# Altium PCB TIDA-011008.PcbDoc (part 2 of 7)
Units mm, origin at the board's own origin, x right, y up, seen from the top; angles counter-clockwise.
Board outline 252 x 205 mm, 4 copper layers (Top Layer, Inner Layer 1, Inner Layer 2, Bottom Layer), stack 1.926 mm thick; 517 components, 293 nets, 1426 pads, 1855 vias.
Unrouted connection lines stored in the file: 4.
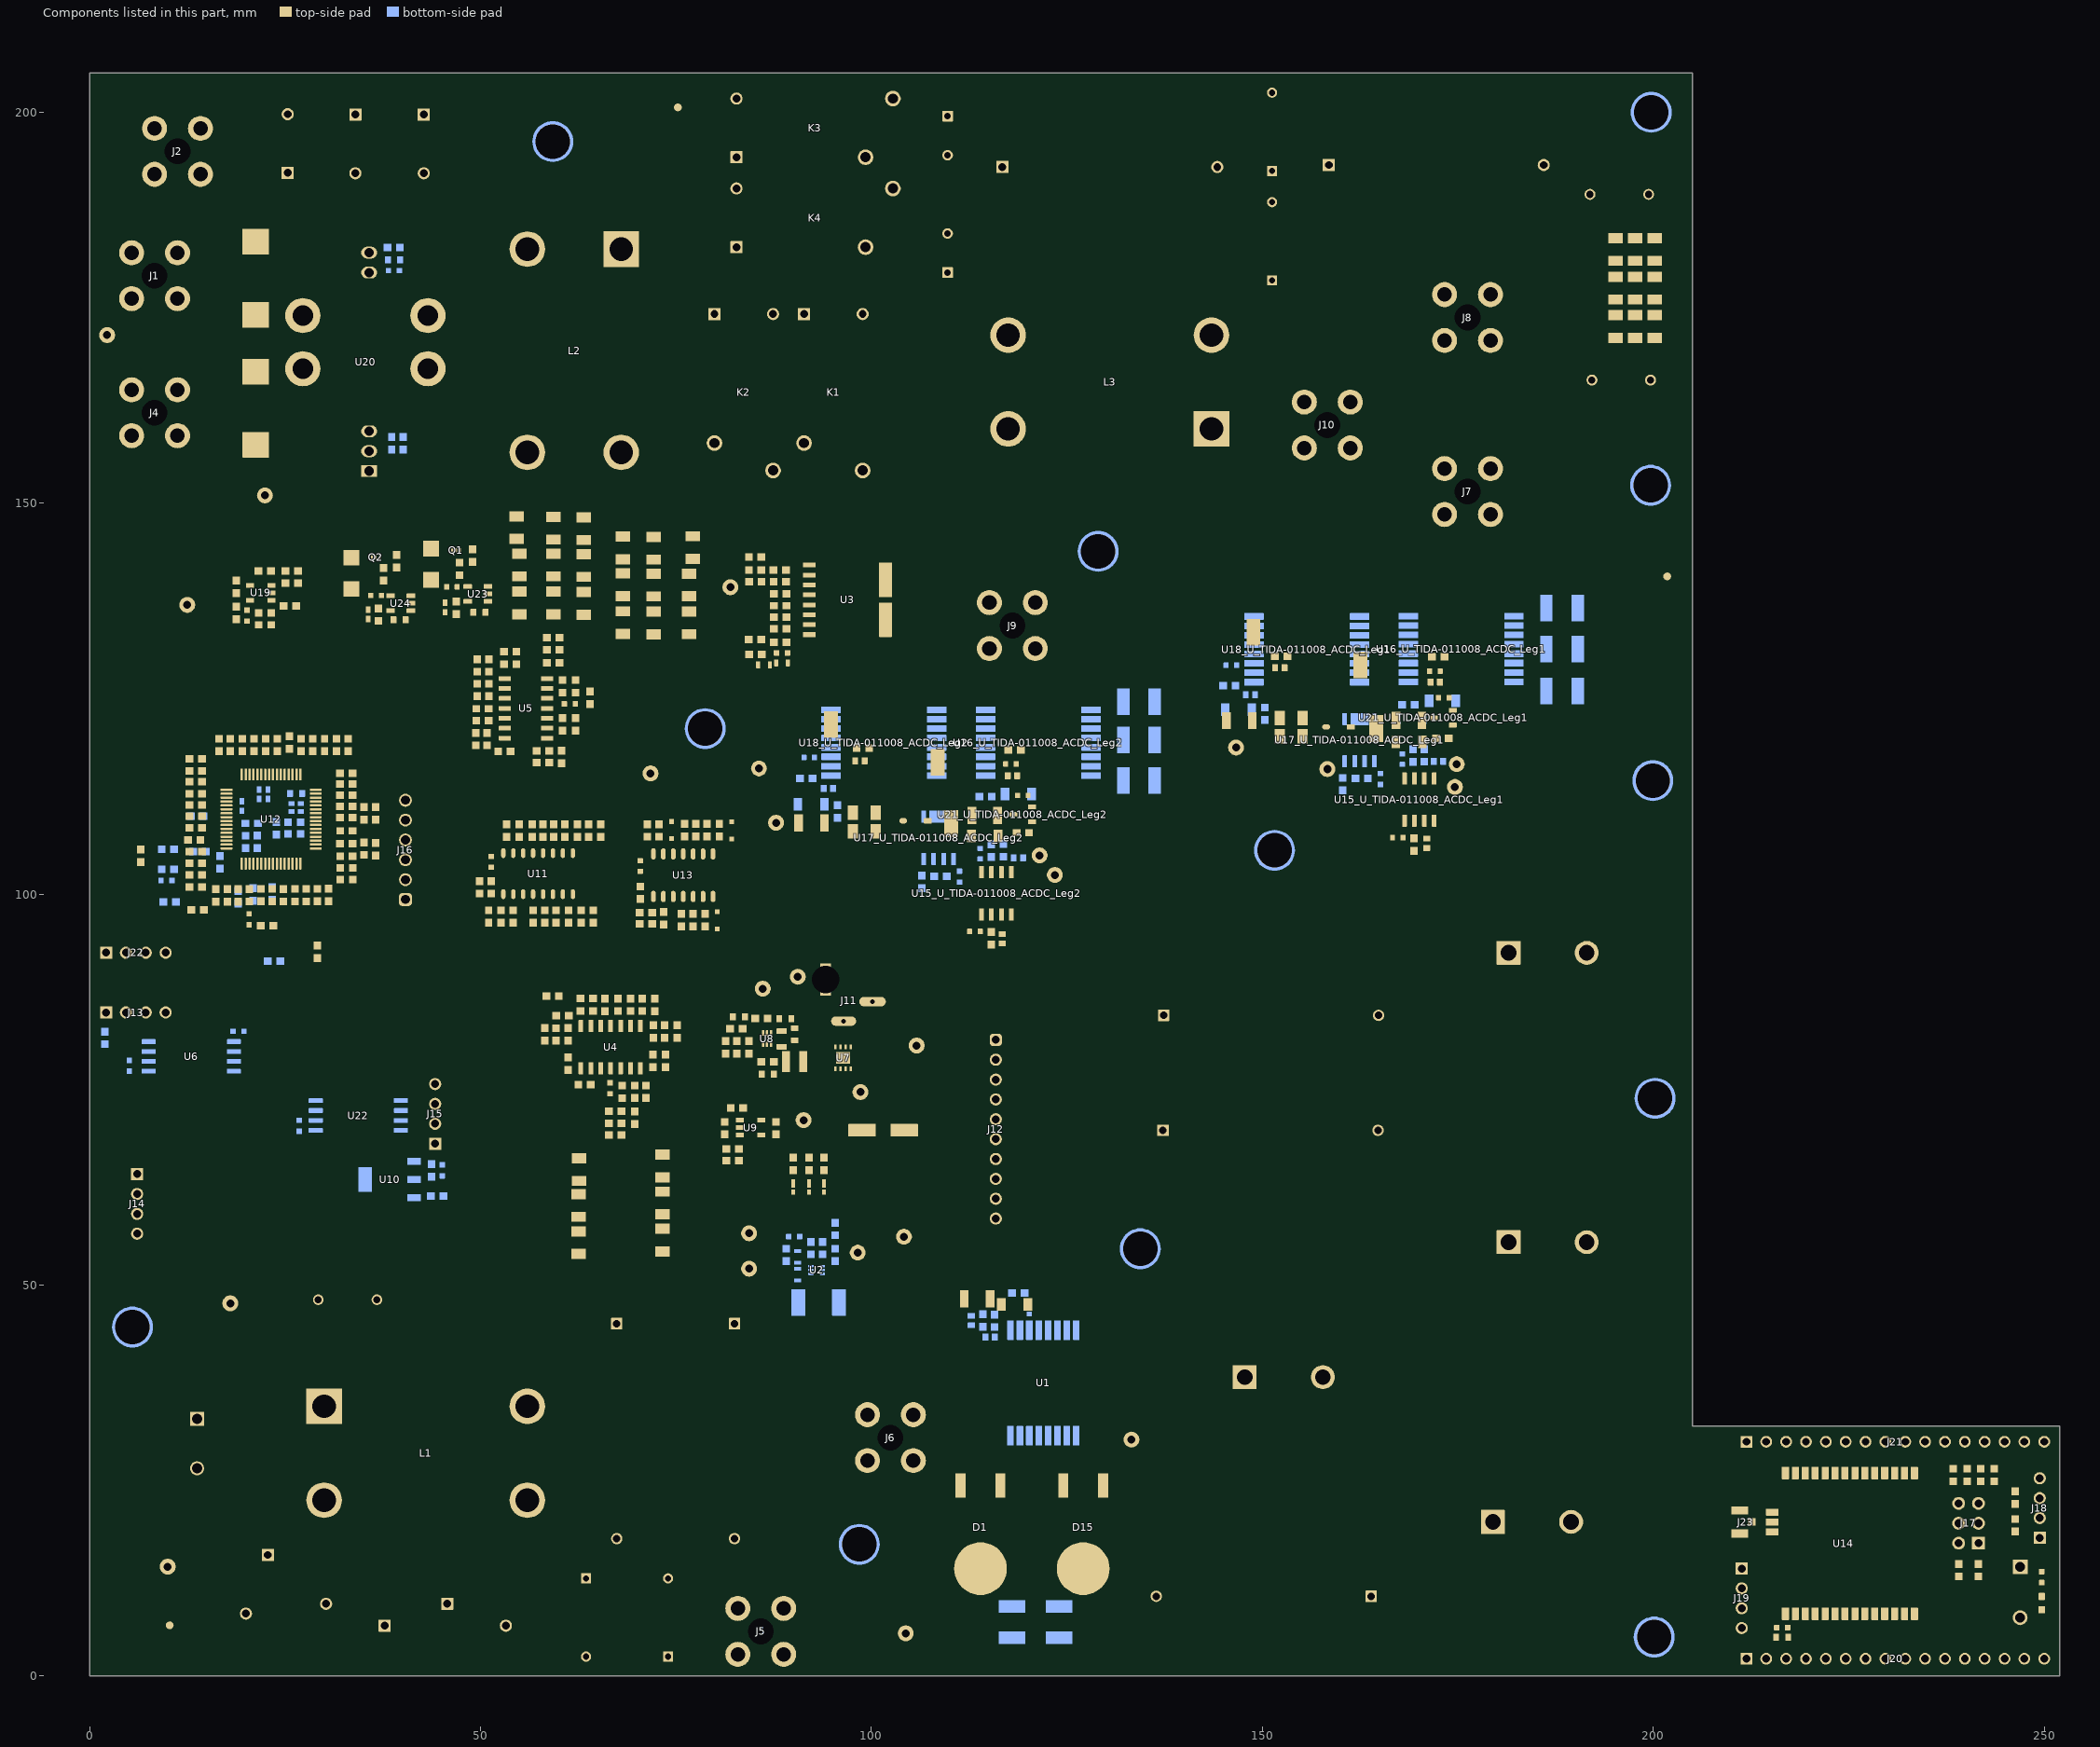
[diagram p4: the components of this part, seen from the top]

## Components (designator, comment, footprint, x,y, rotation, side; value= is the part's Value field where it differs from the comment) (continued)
R128 "RC1608J103CS" 0603 51.047,97.135 r90 top value=10k
R129 "RC1608J103CS" 0603 58.253,97.135 r90 top value=10k
R130 "RC1608J103CS" 0603 62.868,97.135 r90 top value=10k
R131 "RC1608J103CS" 0603 63.831,108.135 r270 top value=10k
R132 "RCS06030000Z0EA" 0603 20.463,99.866 r270 top value=0
R133 "RCS06030000Z0EA" 0603 13.59,102.44 r180 top value=0
R134 "RCS06030000Z0EA" 0603 16.154,99.856 r270 top value=0
R135 "RCS06030000Z0EA" 0603 13.59,103.965 r180 top value=0
R136 "RCS06030000Z0EA" 0603 17.628,99.856 r270 top value=0
R137 "CR0603-JW-472GLF" 0603 70.432,100.181 r90 top value=4.7k
R138 "RCS06030000Z0EA" 0603 19.029,99.856 r270 top value=0
R139 "RCS06030000Z0EA" 0603 23.348,99.872 r270 top value=0
R140 "RCS06030000Z0EA" 0603 13.59,105.465 r180 top value=0
R141 "RCS06030000Z0EA" 0603 13.379,106.959 r180 top value=0
R142 "CRCW060382R0JNEA" 0603 73.432,96.931 r90 top value=82
R143 "RCS06030000Z0EA" 0603 24.811,99.87 r270 top value=0
R144 "RC1608J103CS" 0603 71.182,97.635 r0 top value=10k
R145 "RCS06030000Z0EA" 0603 26.285,99.873 r270 top value=0
R146 "RCS06030000Z0EA" 0603 27.71,99.873 r270 top value=0
R147 "RCS06030000Z0EA" 0603 32.864,103.374 r0 top value=0
R148 "RCS06030000Z0EA" 0603 13.59,109.965 r180 top value=0
R149 "RCS06030000Z0EA" 0603 13.59,108.49 r180 top value=0
R150 "CRCW060382R0JNEA" 0603 77.169,96.681 r90 top value=82
R151 "CRCW060382R0JNEA" 0603 78.719,96.681 r270 top value=82
R152 "RCS06030000Z0EA" 0603 32.864,101.856 r0 top value=0
R153 "CRCW060382R0JNEA" 0603 72.83,108.155 r270 top value=82
R154 "CRCW060382R0JNEA" 0603 76.105,108.181 r90 top value=82
R155 "RC0603JR-072K2L" 0603 32.859,108.102 r0 top value=2.2k
R156 "RC1608J103CS" 0603 32.845,109.808 r0 top value=10k
R157 "RC1608J103CS" 0603 32.847,106.462 r0 top value=10k
R158 "CR0603-JW-472GLF" 0603 13.59,112.865 r180 top value=4.7k
R159 "CRCW060382R0JNEA" 0603 78.979,108.181 r270 top value=82
R160 "CRCW060382R0JNEA" 0603 80.554,108.181 r90 top value=82
R161 "RCS06030000Z0EA" 0603 32.846,112.65 r0 top value=0
R162 "CRCW060310K0JNEA" 0603 241.605,13.55 r270 top value=10k
R163 "CRCW060310K0JNEA" 0603 239.085,13.55 r270 top value=10k
R164 "RC0603FR-100RL" FP-RC0603FR-100RL_0603-MFG 249.69,9.34 r270 top value=0
R165 "CRCW060310K0JNEA" 0603 240.135,25.718 r270 top value=10k
R166 "CRCW060310K0JNEA" 0603 238.36,25.718 r270 top value=10k
R167 "CRCW060310K0JNEA" 0603 246.285,22.84 r90 top value=10k
R168 "CRCW060310K0JNEA" 0603 246.285,19.29 r270 top value=10k
R169 "CR0603-JW-472GLF" 0603 241.865,25.718 r270 top value=4.7k
R170 "CR0603-JW-472GLF" 0603 243.615,25.718 r270 top value=4.7k
R171_U_TIDA-011008_ACDC_Leg1 "CRCW12064R70JNEAHP" 1206 153.694,122.518 r0 top value=4.7 (schematic designator R171)
R171_U_TIDA-011008_ACDC_Leg2 "CRCW12064R70JNEAHP" 1206 99.099,108.043 r0 top value=4.7 (schematic designator R171)
R172_U_TIDA-011008_ACDC_Leg1 "CRCW12064R70JNEAHP" 1206 153.694,120.199 r0 top value=4.7 (schematic designator R172)
R172_U_TIDA-011008_ACDC_Leg2 "CRCW12064R70JNEAHP" 1206 99.099,110.453 r0 top value=4.7 (schematic designator R172)
R173_U_TIDA-011008_ACDC_Leg1 "CRCW06031R00JNEA" 0603 168.678,124.249 r0 bottom value=1.0 (schematic designator R173)
R173_U_TIDA-011008_ACDC_Leg2 "CRCW06031R00JNEA" 0603 114.599,112.492 r0 bottom value=1.0 (schematic designator R173)
R174_U_TIDA-011008_ACDC_Leg1 "CRCW06035R10JNEA" 0603 169.412,106.354 r90 top value=5.1 (schematic designator R174)
R174_U_TIDA-011008_ACDC_Leg2 "CRCW06035R10JNEA" 0603 115.317,94.358 r90 top value=5.1 (schematic designator R174)
R175_U_TIDA-011008_ACDC_Leg1 "RC0603FR-0751RL" 0603 169.267,117.737 r90 bottom value=51.0 (schematic designator R175)
R175_U_TIDA-011008_ACDC_Leg2 "RC0603FR-0751RL" 0603 115.323,105.571 r90 bottom value=51.0 (schematic designator R175)
R176_U_TIDA-011008_ACDC_Leg1 "RC0603FR-0751RL" 0603 170.722,117.75 r90 bottom value=51.0 (schematic designator R176)
R176_U_TIDA-011008_ACDC_Leg2 "RC0603FR-0751RL" 0603 116.861,105.596 r90 bottom value=51.0 (schematic designator R176)
R177_U_TIDA-011008_ACDC_Leg1 "RC0603FR-0743K2L" 0603 172.496,130.388 r180 top value=43.2k (schematic designator R177)
R177_U_TIDA-011008_ACDC_Leg2 "RC0603FR-0743K2L" 0603 118.315,118.44 r180 top value=43.2k (schematic designator R177)
R178_U_TIDA-011008_ACDC_Leg1 "CRCW060356R0JNEA" 0603 160.298,114.07 r90 bottom value=56 (schematic designator R178)
R178_U_TIDA-011008_ACDC_Leg2 "CRCW060356R0JNEA" 0603 106.455,101.574 r90 bottom value=56 (schematic designator R178)
R179_U_TIDA-011008_ACDC_Leg1 "CRCW06031R00JNEA" 0603 150.317,123.073 r90 bottom value=1.0 (schematic designator R179)
R179_U_TIDA-011008_ACDC_Leg2 "CRCW06031R00JNEA" 0603 95.648,110.59 r90 bottom value=1.0 (schematic designator R179)
R180_U_TIDA-011008_ACDC_Leg1 "RC0603FR-0751RL" 0603 145.777,126.662 r0 bottom value=51.0 (schematic designator R180)
R180_U_TIDA-011008_ACDC_Leg2 "RC0603FR-0751RL" 0603 91.678,114.803 r0 bottom value=51.0 (schematic designator R180)
R181_U_TIDA-011008_ACDC_Leg1 "RC0603FR-0743K2L" 0603 152.398,130.429 r180 top value=43.2k (schematic designator R181)
R181_U_TIDA-011008_ACDC_Leg2 "RC0603FR-0743K2L" 0603 98.914,118.683 r180 top value=43.2k (schematic designator R181)
R182 "RCS06030000Z0EA" 0603 13.59,117.319 r180 top value=0
R183 "RCS06030000Z0EA" 0603 32.846,111.25 r0 top value=0
R184 "RCS06030000Z0EA" 0603 27.04,119.077 r90 top value=0
R185 "RCS06030000Z0EA" 0603 13.59,115.769 r180 top value=0
R186 "RCS06030000Z0EA" 0603 21.908,99.884 r270 top value=0
R187 "RCS06030000Z0EA" 0603 25.56,119.404 r90 top value=0
R188 "RCS06030000Z0EA" 0603 13.59,100.915 r180 top value=0
R189 "RCS06030000Z0EA" 0603 32.856,104.856 r0 top value=0
R190 "RC1608J103CS" 0603 35.088,110.352 r270 top value=10k
R191 "RC1608J103CS" 0603 35.088,105.827 r90 top value=10k
R192 "RCS06030000Z0EA" 0603 36.588,110.352 r270 top value=0
R193 "RCS06030000Z0EA" 0603 36.586,105.731 r90 top value=0
R194 "RCG060310K0FKEA" 0603 18.747,139.3 r90 top value=10.0k
R195 "RC0603FR-0780R6L" 0603 25.608,136.855 r0 top value=80.6
R196 "RCG060310K0FKEA" 0603 22.4,141.35 r180 top value=10.0k
R197 "RCG060310K0FKEA" 0603 25.865,139.807 r180 top value=10.0k
R198 "RCG060310K0FKEA" 0603 22.435,135.963 r180 top value=10.0k
R199 "RCS06030000Z0EA" 0603 13.593,111.434 r180 top value=0
R200 "RCS06030000Z0EA" 0603 29.145,99.881 r270 top value=0
R201 "CRCW060356R0JNEA" 0603 40.104,157.656 r270 bottom value=56
R202 "RCS06030000Z0EA" 0603 30.593,99.897 r270 top value=0
SW1 "FSMH" FP-FSMH_PTH_SW_6MM0_3MM5-MFG 246.94,10.72 r270 top
TP1 "5001" Keystone5001 10,14 r0 top
TP2 "5001" Keystone5001 133.266,30.25 r90 top
TP3 "5001" Keystone5001 104.393,5.479 r180 top
TP4 "5001" Keystone5001 104.166,56.191 r180 top
TP5 "5001" Keystone5001 98.603,74.693 r180 top
TP6 "5001" Keystone5001 18,47.681 r90 top
TP7 "5001" Keystone5001 105.793,80.646 r90 top
TP8 "5001" Keystone5001 98.25,54.162 r0 top
TP9 "5001" Keystone5001 84.358,52.109 r0 top
TP10 "5001" Keystone5001 84.358,56.642 r270 top
TP11 "5001" Keystone5001 2.25,171.5 r180 top
TP12 "5001" Keystone5001 22.435,151 r180 top
TP13 "5001" Keystone5001 71.757,115.444 r90 top
TP14 "5001" Keystone5001 81.962,139.255 r90 top
TP15_U_TIDA-011008_ACDC_Leg1 "5017" Keystone_5017 164.589,121.178 r90 top (schematic designator TP15)
TP15_U_TIDA-011008_ACDC_Leg2 "5017" Keystone_5017 110.206,109.035 r90 top (schematic designator TP15)
TP20 "5001" Keystone5001 91.33,71.108 r90 top
TP22 "5001" Keystone5001 86.108,87.915 r90 top
TP23 "5001" Keystone5001 90.589,89.44 r90 top
TP24 "5001" Keystone5001 12.5,137 r90 top
TP26_U_TIDA-011008_ACDC_Leg1 "5001" Keystone5001 174.641,113.714 r180 top (schematic designator TP26)
TP26_U_TIDA-011008_ACDC_Leg2 "5001" Keystone5001 123.464,102.463 r180 top (schematic designator TP26)
TP28_U_TIDA-011008_ACDC_Leg1 "5001" Keystone5001 174.868,116.631 r180 top (schematic designator TP28)
TP28_U_TIDA-011008_ACDC_Leg2 "5001" Keystone5001 121.517,104.963 r180 top (schematic designator TP28)
TP29_U_TIDA-011008_ACDC_Leg1 "5017" Keystone_5017 162.549,129.329 r90 top (schematic designator TP29)
TP29_U_TIDA-011008_ACDC_Leg2 "5017" Keystone_5017 108.459,116.853 r90 top (schematic designator TP29)
TP30_U_TIDA-011008_ACDC_Leg1 "5001" Keystone5001 146.643,118.758 r180 top (schematic designator TP30)
TP30_U_TIDA-011008_ACDC_Leg2 "5001" Keystone5001 85.618,116.081 r90 top (schematic designator TP30)
TP31_U_TIDA-011008_ACDC_Leg1 "5001" Keystone5001 87.807,109.14 r90 top (schematic designator TP31)
TP31_U_TIDA-011008_ACDC_Leg2 "5001" Keystone5001 158.328,116 r180 top (schematic designator TP31)
TP32_U_TIDA-011008_ACDC_Leg1 "5017" Keystone_5017 94.842,121.679 r90 top (schematic designator TP32)
TP32_U_TIDA-011008_ACDC_Leg2 "5017" Keystone_5017 148.863,133.5 r90 top (schematic designator TP32)
U1 "LMG3660R040KLGR" KLG0016A-MFG 122,37.5 r90 bottom
U2 "INA185A2IDRLR" DRL0006A 93,51.942 r180 bottom
U3 "TMCS1123B1QDVGR" DVG0010A-MFG 96.928,137.641 r180 top
U4 "TLV9054IDR" D0014A-MFG 66.654,80.443 r90 top
U5 "TLV9054IDR" D0014A-MFG 55.826,123.764 r180 top
U6 "ISO6421FDWVR" DWV0008A-MFG 13.01,79.25 r180 bottom
U7 "TVS1401DRBR" DRB0008A 96.383,79.079 r90 top
U8 "TPS562207DRLR" DRL0006A 86.658,81.525 r90 top
U9 "TLV75533PDBVR" DBV0005A_N 84.558,70.158 r0 top
U10 "TLV1117LV33DCYR" DCY0004A_N 38.387,63.514 r180 bottom
U11 "SN74HC365DR" D0016A_L 57.368,102.635 r90 top
U12 "F28P551SG5PM" PM0064A-MFG 23.215,109.602 r0 top
U13 "SN74LV125ADR" D0014A_L 75.932,102.431 r90 top
U14 "WS8712x-C5" FP-WS8712x-C5_SMD31-MFG 225.82,16.975 r90 top
U15_U_TIDA-011008_ACDC_Leg1 "ISO6721RFBDR" D0008A-MFG 170.087,112.104 r90 top (schematic designator U15)
U15_U_TIDA-011008_ACDC_Leg2 "ISO6721RFBDR" D0008A-MFG 115.992,100.108 r90 top (schematic designator U15)
U16_U_TIDA-011008_ACDC_Leg1 "LMG3660R040KLGR" KLG0016A-MFG 175.437,131.354 r180 bottom (schematic designator U16)
U16_U_TIDA-011008_ACDC_Leg2 "LMG3660R040KLGR" KLG0016A-MFG 121.355,119.376 r180 bottom (schematic designator U16)
U17_U_TIDA-011008_ACDC_Leg1 "ISOTMP35BEDFQRQ1" DFQ0007A-MFG 162.449,119.704 r90 bottom (schematic designator U17)
U17_U_TIDA-011008_ACDC_Leg2 "ISOTMP35BEDFQRQ1" DFQ0007A-MFG 108.605,107.208 r90 bottom (schematic designator U17)
U18_U_TIDA-011008_ACDC_Leg1 "LMG3660R040KLGR" KLG0016A-MFG 155.688,131.317 r180 bottom (schematic designator U18)
U18_U_TIDA-011008_ACDC_Leg2 "LMG3660R040KLGR" KLG0016A-MFG 101.595,119.373 r180 bottom (schematic designator U18)
U19 "TLV9001IDBVR" DBV0005A_N 21.9,138.544 r180 top
U20 "STK-0.3P/M1S-x:20" FP-STK-0.3P%2FM1S-x_20_STK-x.xP%2FM1S-x-MFG 34.662,168.25 r270 top
U21_U_TIDA-011008_ACDC_Leg1 "TLV76050DBZR" DBZ0003A_N 173.167,122.581 r180 top (schematic designator U21)
U21_U_TIDA-011008_ACDC_Leg2 "TLV76050DBZR" DBZ0003A_N 119.367,110.215 r180 top (schematic designator U21)
U22 "ISO6421FDWVR" DWV0008A-MFG 34.38,71.7 r0 bottom
U23 "UCC44273DBVR" DBV0005A-MFG 49.665,138.393 r180 top
U24 "UCC44273DBVR" DBV0005A-MFG 39.801,137.202 r180 top

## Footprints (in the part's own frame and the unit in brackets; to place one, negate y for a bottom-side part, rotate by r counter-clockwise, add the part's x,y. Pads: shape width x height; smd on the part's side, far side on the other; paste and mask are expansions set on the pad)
0402 [mm] "0402 from SM-752 data"
  rect 0.8x0.6 smd: 1(-0.6,0) 2(0.6,0)
  silkscreen extent -1.22,-0.52 1.22,0.52, body extent -0.55,-0.3 0.55,0.3, height 0.6
0603 [mm] "0603 from SM-752 data"
  rect 1x0.95 smd: 1(-0.8,0) 2(0.8,0)
  silkscreen extent -1.52,-0.69 1.52,0.69, body extent -0.87,-0.47 0.87,0.47, height 1
1206 [mm] "1206 from SM-752 data"
  rect 1.3x1.85 smd: 1(-1.45,0) 2(1.45,0)
  silkscreen extent -2.4,-1.21 2.4,1.21, body extent -1.7,-0.9 1.7,0.9, height 1.35
1206_180 [mm] "1206_180"
  rect 1.1x1.6 smd: 1(-1.7,0) 2(1.7,0)
  silkscreen extent -0.9,-1 0.9,1, body extent -1.75,-0.95 1.75,0.95, height 1.8
1210_280 [mm] "SMD, 2-Leads, Body 3.6x2.8mm, Height 2.8mm"
  rect 1.1x2.2 smd: 1(-1.65,0) 2(1.65,0)
  silkscreen extent -0.84,-1.4 0.84,1.4, body extent -1.8,-1.4 1.8,1.4, height 2.8
1812_254 [mm] "SMD, 2-Leads, Body 4.8x3.4mm"
  rect 1.6x3.4 smd: 1(-2,0) 2(2,0)
  silkscreen extent -0.8,-1.7 0.8,1.7, body extent -2.4,-1.7 2.4,1.7, height 2.54
CE_Mark_5mm [mm] "Minimum text height for CE Mark"
  silkscreen extent -3.5,-2.5 3.5,2.5
CK45_1250x600x1650 [mm] "TH, 2-Leads, Dia 12.5mm, Pin Spacing 7.5mm"
  round 1.35 hole 0.9: 1(-3.75,0) 2(3.75,0)
  body extent -6.25,-3 6.25,3, height 16.25
CONN_UFL-R-SMT-1 [mm] "Hirose recommended land pattern http://www.hirose.co.jp/cataloge_hp/e32119372.pdf 2009.2"
  rect 1.05x1 smd paste-0.1 mask-0.1: 1(-1.525,0)
  rect 2x0.9 on Top Paste: 2(0,1.5) 3(0,-1.5)
  rect 2x0.9 on Top Solder: 2(0,1.5) 3(0,-1.5)
  rect 2.2x1.05 smd paste-2 mask-2: 2(0,1.475) 3(0,-1.475)
  Top Layer keep-out region: -0.8,-0.7 1.1,-0.7 1.1,0.7 -0.8,0.7
  silkscreen extent -1.7,-1.7 1.7,1.7, body extent -1.55,-1.5 1.55,1.5, height 1.27
D0008A-MFG [mm] "Recommended Land Pattern"
  rrect17% 1.55x0.6 smd paste+0 mask+0: 1(-2.7,1.905) 2(-2.7,0.635) 3(-2.7,-0.635) 4(-2.7,-1.905) 5(2.7,-1.905) 6(2.7,-0.635) 7(2.7,0.635) 8(2.7,1.905)
  silkscreen extent -4.17,-2.5 1.5,2.5, body extent -3,-2.45 3,2.45, height 1.75
D0014A-MFG [mm] "Recommended Land Pattern"
  rrect17% 1.55x0.6 smd paste+0 mask+0: 1(-2.7,3.81) 2(-2.7,2.54) 3(-2.7,1.27) 4(-2.7,0) 5(-2.7,-1.27) 6(-2.7,-2.54) 7(-2.7,-3.81) 8(2.7,-3.81) 9(2.7,-2.54) 10(2.7,-1.27) 11(2.7,0) 12(2.7,1.27) 13(2.7,2.54) 14(2.7,3.81)
  silkscreen extent -2.82,-4.38 1.5,4.81, body extent -3,-4.33 3,4.33, height 1.75
D0014A_L [mm] "SOIC, 14-Leads, Body 8.7x3.9mm, Pitch 1.27mm, IPC High Density"
  oval 1.45x0.6 smd: 1(-2.725,3.81) 2(-2.725,2.54) 3(-2.725,1.27) 4(-2.725,0) 5(-2.725,-1.27) 6(-2.725,-2.54) 7(-2.725,-3.81) 8(2.725,-3.81) 9(2.725,-2.54) 10(2.725,-1.27) 11(2.725,0) 12(2.725,1.27) 13(2.725,2.54) 14(2.725,3.81)
  silkscreen extent -3.3,-4.4 0.9,4.4, body extent -3.02,-4.32 3.02,4.32, height 1.6
D0016A_L [mm] "SOIC, 16-Leads, Body 9.9x3.9mm, Pitch 1.27mm, IPC High Density"
  oval 1.25x0.55 smd: 1(-2.625,4.445) 2(-2.625,3.175) 3(-2.625,1.905) 4(-2.625,0.635) 5(-2.625,-0.635) 6(-2.625,-1.905) 7(-2.625,-3.175) 8(-2.625,-4.445) 9(2.625,-4.445) 10(2.625,-3.175) 11(2.625,-1.905) 12(2.625,-0.635) 13(2.625,0.635) 14(2.625,1.905) 15(2.625,3.175) 16(2.625,4.445)
  silkscreen extent -3.1,-5 0.9,5, body extent -3,-4.95 3,4.95, height 1.6
DBV0005A-MFG [mm]
  rrect17% 1.1x0.6 smd paste+0 mask+0: 1(-1.3,0.95) 2(-1.3,0) 3(-1.3,-0.95) 4(1.3,-0.95) 5(1.3,0.95)
  silkscreen extent -2.58,-1.53 0.87,1.53, body extent -1.95,-1.78 1.95,1.78, height 0.25
DBV0005A_N [mm] "SOT23, 5-Leads, Body 2.9x1.6mm, Pitch 0.95mm, Lead Span 2.8mm, IPC Medium Density"
  rrect17% 1x0.6 smd: 1(-1.375,0.95) 2(-1.375,0) 3(-1.375,-0.95) 4(1.375,-0.95) 5(1.375,0.95)
  silkscreen extent -0.25,-1.55 0.25,1.55, body extent -1.42,-1.46 1.42,1.46, height 1.09
DBZ0003A_N [mm] "SOT23, 3-Leads, Body 2.9x1.3mm, Pitch 0.95mm, Lead Span 2.4mm, IPC Medium Density"
  rrect17% 1x0.6 smd: 1(-1.2,0.95) 2(-1.2,-0.95) 3(1.2,0)
  silkscreen extent 0.2,-1.5 0.7,1.5, body extent -1.26,-1.46 1.26,1.46, height 0.98
DCY0004A_N [mm] "SOT223/SC73, 4-Leads, Body 6.5x3.5mm, Pitch 2.3mm, Lead Span 7mm, IPC Medium Density"
  rrect11% 1.75x0.9 smd: 1(-3.125,2.3) 2(-3.125,0) 3(-3.125,-2.3)
  rrect6% 1.75x3.2 smd: 4(3.125,0)
  silkscreen extent -3.03,-3.35 1.4,3.47, body extent -3.48,-3.25 3.48,3.25, height 1.68
DFQ0007A-MFG [mm]
  rrect17% 1.55x0.6 smd paste+0 mask+0: 1(-2.7,1.905) 2(-2.7,0.635) 3(-2.7,-0.635) 4(-2.7,-1.905) 5(2.7,-1.905) 7(2.7,1.905)
  rrect6% 1.55x2.36 smd paste+0 mask+0: 6(2.7,0)
  silkscreen extent -4.14,-2.5 1.55,2.5, body extent -3.01,-2.45 3.01,2.45, height 1.75
DRB0008A [mm] "VSON-8"
  rrect32% 0.6x0.31 smd: 1(-1.4,0.975) 2(-1.4,0.325) 3(-1.4,-0.325) 4(-1.4,-0.975) 5(1.4,-0.975) 6(1.4,-0.325) 7(1.4,0.325) 8(1.4,0.975)
  rrect7% 1.5x1.75 smd paste-0.75: 9(0,0)
  Top Layer region: -0.7,-0.875 -0.49,-0.875 -0.471,-0.879 -0.455,-0.89 -0.444,-0.906 -0.44,-0.925 -0.44,-0.925 -0.44,-1.65 -0.436,-1.669 -0.425,-1.685 -0.409,-1.696 -0.39,-1.7 -0.39,-1.7 -0.26,-1.7 -0.241,-1.696 -0.225,-1.685 -0.214,-1.669 -0.21,-1.65 -0.21,-1.65 -0.21,-0.925 -0.206,-0.906 -0.195,-0.89 -0.179,-0.879 -0.16,-0.875 -0.16,-0.875 0.16,-0.875 0.179,-0.879 0.195,-0.89 0.206,-0.906 0.21,-0.925 0.21,-0.925 0.21,-1.65 0.21,-1.65 0.214,-1.669 0.225,-1.685 0.241,-1.696 0.26,-1.7 0.26,-1.7 0.39,-1.7 0.409,-1.696 0.425,-1.685 0.436,-1.669 0.44,-1.65 0.44,-1.65 0.44,-0.925 0.444,-0.906 0.455,-0.89 0.471,-0.879 0.49,-0.875 0.49,-0.875 0.7,-0.875 0.719,-0.871 0.735,-0.86 0.746,-0.844 0.75,-0.825 0.75,-0.825 0.75,0.825 0.746,0.844 0.735,0.86 0.719,0.871 0.7,0.875 0.7,0.875 0.49,0.875 0.471,0.879 0.455,0.89 0.444,0.906 0.44,0.925 0.44,0.925 0.44,1.65 0.436,1.669 0.425,1.685 0.409,1.696 0.39,1.7 0.39,1.7 0.26,1.7 0.241,1.696 0.225,1.685 0.214,1.669 0.21,1.65 0.21,1.65 0.21,1.65 0.21,0.925 0.206,0.906 0.195,0.89 0.179,0.879 0.16,0.875 0.16,0.875 -0.16,0.875 -0.179,0.879 -0.195,0.89 -0.206,0.906 -0.21,0.925 -0.21,0.925 -0.21,1.65 -0.214,1.669 -0.225,1.685 -0.241,1.696 -0.26,1.7 -0.26,1.7 -0.39,1.7 -0.409,1.696 -0.425,1.685 -0.436,1.669 -0.44,1.65 -0.44,1.65 -0.44,0.925 -0.444,0.906 -0.455,0.89 -0.471,0.879 -0.49,0.875 -0.49,0.875 -0.7,0.875 -0.719,0.871 -0.735,0.86 -0.746,0.844 -0.75,0.825 -0.75,0.825 -0.75,-0.825 -0.746,-0.844 -0.735,-0.86 -0.719,-0.871 -0.7,-0.875
  silkscreen extent -1.73,-1.73 1.73,1.73, body extent -1.5,-1.5 1.5,1.5, height 0.77
DRL0006A [mm] "SOTFL, 6-Flat Leads, Body 1.2x1.6x0.6mm, Pitch 0.5mm, TI recommended"
  rrect33% 0.67x0.3 smd: 1(-0.74,0.5) 2(-0.74,0) 3(-0.74,-0.5) 4(0.74,-0.5) 5(0.74,0) 6(0.74,0.5)
  silkscreen extent -0.9,-0.95 0.5,0.95, body extent -0.8,-0.8 0.8,0.8, height 0.61
DVG0010A-MFG [mm]
  rrect6% 1.65x4.41 smd paste+0 mask+0: 1(-4.875,2.54) 2(-4.875,-2.54)
  rrect17% 1.65x0.6 smd paste+0 mask+0: 3(4.875,-4.445) 4(4.875,-3.175) 5(4.875,-1.905) 6(4.875,-0.635) 7(4.875,0.635) 8(4.875,1.905) 9(4.875,3.175) 10(4.875,4.445)
  silkscreen extent -6.35,-5.25 3.8,5.25, body extent -5.8,-5.5 5.8,5.5, height 0.25
DWV0008A-MFG [mm] "Recommended Land Pattern"
  rrect17% 1.8x0.6 smd paste+0 mask+0: 1(-5.45,1.905) 2(-5.45,0.635) 3(-5.45,-0.635) 4(-5.45,-1.905) 5(5.45,-1.905) 6(5.45,-0.635) 7(5.45,0.635) 8(5.45,1.905)
  silkscreen extent -7.02,-2.98 3.8,2.98, body extent -5.75,-2.93 5.75,2.93, height 2.8
E_900x700x900 [mm] "TH, 2- Leads, Body 9x7mm, Pin Spacing 7.5mm"
  round 1.4 hole 0.9: 1(-3.75,0) 2(3.75,0)
  silkscreen extent -4.5,-3.5 4.5,3.5, body extent -4.49,-3.5 4.49,3.5, height 11.96
FCC_disclaimer [mm]
Fiducial10-20 [mm]
  round 1 smd mask+0.5: 1(0,0)
  Top Layer keep-out circle w1.178: c0,0 r0.5
FP-9774030960R_SPACER-MFG#1 [mm] "Recommended Land Pattern"
  round 5.245 smd paste-1000 mask-1000: 1(0,0)
  round 4.4 hole 4.4 unplated paste-2539.97 mask+0: ""(0,0)
  Top Layer lines w1.5: 2.035,-2.135 cw(c0,0) -2.378,-1.746 cw(c0,0) -2.95,0 cw(c0,0) 2.035,-2.135
  silkscreen extent -4.08,-4.07 4.07,4.07, body extent -3,-3 2.99,3, height 3.1
FP-9774030960R_SPACER-MFG#2 [mm] "Recommended Land Pattern"
  round 5.245 smd paste-1000 mask-1000: 1(0,0)
  round 4.4 hole 4.4 unplated paste-2539.97 mask+0: ""(0,0)
  Top Layer circle w1.5: c0,0 r2.95
  silkscreen extent -4.08,-4.07 4.07,4.07, body extent -3,-3 2.99,3, height 3.1
FP-694106402002_CONN_PWR_10MM7_9MM0-MFG [mm]
  rrect7% 1.4x4.1 hole 3.5 slot 0.8 at 0 deg paste-1000 mask+0: 1(-3.5,1.15)
  rrect100% 3.2x1.2 hole 0.6 slot 2.6 at 0 deg paste-1000 mask+0: 2(-1.2,-4.15)
  rrect100% 3.4x1.2 hole 0.6 slot 2.8 at 0 deg paste-1000 mask+0: 3(2.5,-1.65)
  silkscreen extent -4.75,-5.5 4.75,5.5, body extent -4.85,-5.6 4.85,5.6, height 0.25
FP-ALH82D161DD600_RADIAL-MFG [mm]
  rrect3% 3.05x3.05 hole 2 paste-1000 mask+0: 1(-5,0)
  round 3.05 hole 2 paste-1000 mask+0: 2(5,0)
  silkscreen extent -18,-18 18,18, body extent -18.1,-18.1 18.1,18.1, height 0.25
FP-B72314S2461K101_RADIAL-MFG [mm] "Recommended Land Pattern"
  rrect6% 1.55x1.55 hole 1 paste-2539.97 mask+0: 1(-3.75,1.4)
  round 1.55 hole 1 paste-2539.97 mask+0: 2(3.75,-1.4)
  silkscreen extent -7,-4.1 7,4.1, body extent -7,-4.1 7,4.1, height 18
FP-C0603C221J5GAC7867_0603-MFG [mm]
  rrect13% 0.75x0.9 smd paste+0 mask+0: 1(-0.6,0) 2(0.6,0)
  silkscreen extent -0.87,-0.82 0.87,0.82, body extent -0.8,-0.4 0.8,0.4, height 0.87
FP-C1608X8R1E104K080AA_0603-MFG [mm]
  rrect14% 0.7x0.7 smd paste+0 mask+0: 1(-0.7,0) 2(0.7,0)
  silkscreen extent -0.8,-0.75 0.8,0.75, body extent -0.8,-0.4 0.8,0.4, height 0.9
FP-CRCW06031K00FKEAC_0603-MFG [mm]
  rrect20% 0.5x0.9 smd paste+0 mask+0: 1(-0.75,0) 2(0.75,0)
  silkscreen extent -0.13,-0.45 0.13,0.45, body extent -0.8,-0.4 0.8,0.4, height 0.55
FP-CRCW060310K0FKEAC_0603-MFG [mm] "Recommended Land Pattern"
  rrect20% 0.5x0.9 smd paste+0 mask+0: 1(-0.75,0) 2(0.75,0)
  silkscreen extent -0.13,-0.45 0.13,0.45, body extent -0.77,-0.4 0.77,0.4, height 0.5
FP-CSS2H-2512K-2L00F_2512-MFG [mm]
  rrect6% 1.8x3.4 smd paste+0 mask+0: 1(-2.6,0) 2(2.6,0)
  silkscreen extent -1.33,-1.63 1.33,1.63, body extent -3.17,-1.53 3.17,1.53, height 1.09
FP-FCS2SDS305K050I490B_RADIAL-MFG [mm] "Recommended Land Pattern"
  rrect7% 1.45x1.45 hole 0.95 paste-2539.97 mask+0: 1(-13.75,0)
  round 1.45 hole 0.95 paste-2539.97 mask+0: 2(13.75,0)
  silkscreen extent -16,-5.5 16,5.5, body extent -16,-5.5 16,5.5, height 20
FP-FCS2SDS505K050IC90B_RADIAL-MFG [mm] "Recommended Land Pattern"
  rrect7% 1.45x1.45 hole 0.95 paste-2539.97 mask+0: 1(-13.75,0)
  round 1.45 hole 0.95 paste-2539.97 mask+0: 2(13.75,0)
  silkscreen extent -16,-7 16,7, body extent -16,-7 16,7, height 28
FP-FCS3BAX475K050II90B_RADIAL-MFG [mm] "Recommended Land Pattern"
  rrect6% 1.55x1.55 hole 1 paste-2539.97 mask+0: 1(-13.75,0)
  round 1.55 hole 1 paste-2539.97 mask+0: 2(13.75,0)
  silkscreen extent -16.5,-11.5 16.5,11.5, body extent -16,-11 16,11, height 38
FP-FSMH_PTH_SW_6MM0_3MM5-MFG [mm] "Recommended Land Pattern"
  rrect5% 1.89x1.89 hole 1.24 paste-2539.97 mask+0: 1(-3.25,0)
  round 1.89 hole 1.24 paste-2539.97 mask+0: 2(3.25,0)
  silkscreen extent -3.15,-1.9 3.15,1.9, body extent -3.95,-1.75 3.95,1.75, height 5.62
"FP-G5PZ-1A-E DC12_PTH_RELAY_23MM8_10MM3-MFG" [mm]
  rrect6% 1.55x1.55 hole 1 paste-1000 mask+0: 1(-10,-3.75)
  round 2 hole 1.3 paste-1000 mask+0: 2(6.5,-3.75) 3(10,3.75)
  round 1.55 hole 1 paste-1000 mask+0: 4(-10,3.75)
  silkscreen extent -12.72,-5.25 12,5.25, body extent -12.1,-5.35 12.1,5.35, height 0.25
FP-GCE21BR71H104KA01L_0805-MFG [mm]
  rrect14% 0.7x1.3 smd paste+0 mask+0: 1(-1,0) 2(1,0)
  silkscreen extent -0.28,-0.72 0.28,0.72, body extent -1.45,-0.82 1.45,0.82, height 0.25
FP-GCM188R71H104KA57J_0603-MFG [mm]
  rrect15% 0.65x0.7 smd paste+0 mask+0: 1(-0.675,0) 2(0.675,0)
  silkscreen extent -0.85,-0.75 0.85,0.75, body extent -0.8,-0.4 0.8,0.4, height 0.9
FP-GRM188C61E226ME01J_0603-MFG [mm]
  rrect13% 0.75x0.9 smd paste+0 mask+0: 1(-0.775,0) 2(0.775,0)
  silkscreen extent -0.9,-0.9 0.9,0.9, body extent -1.25,-0.6 1.25,0.6, height 0.25
FP-GRM188Z71A106KA73D_0603-MFG [mm] "Recommended Land Pattern"
  rrect13% 0.75x0.9 smd paste+0 mask+0: 1(-0.775,0) 2(0.775,0)
  silkscreen extent -0.9,-0.9 0.9,0.9, body extent -0.8,-0.4 0.8,0.4, height 1
FP-IsoM5-275-B-L2_RADIAL-MFG [mm]
  rrect6% 1.55x1.55 hole 1 paste-1000 mask+0: 1(-3.75,0)
  round 1.55 hole 1 paste-1000 mask+0: 2(3.75,0)
  silkscreen extent -8.5,-3.15 8.5,3.15, body extent -8.6,-3.25 8.6,3.25, height 0.25
"FP-KG DELLS1.22-JGKH-24_0603-MFG" [mm]
  rrect20% 1.05x0.5 smd paste-1000 mask+0: 1(-0.47,0)
  rrect20% 0.7x0.5 smd paste-1000 mask+0: 2(0.645,0)
  silkscreen extent -1.67,-0.63 0.75,0.63, body extent -1.09,-0.55 1.09,0.55, height 0.25
FP-MH1608-601Y_0603-MFG [mm]
  rrect14% 0.7x0.7 smd paste+0 mask+0: 1(-0.7,0) 2(0.7,0)
  silkscreen extent -0.87,-0.8 0.87,0.8, body extent -0.8,-0.4 0.8,0.4, height 1
FP-PTCEL13R600LBE_RADIAL-MFG [mm]
  rrect7% 1.35x1.35 hole 0.85 paste-1000 mask+0: 1(-2.5,0)
  round 1.35 hole 0.85 paste-1000 mask+0: 2(2.5,0)
  silkscreen extent -6.75,-3.5 6.75,3.5, body extent -6.85,-3.6 6.85,3.6, height 0.25
FP-R413F168050T0K_RADIAL-MFG [mm]
  rrect8% 1.3x1.3 hole 0.8 paste-1000 mask+0: 1(-5,0)
  round 1.3 hole 0.8 paste-1000 mask+0: 2(5,0)
  silkscreen extent -6.65,-3.1 6.65,3.1, body extent -6.75,-3.2 6.75,3.2, height 0.25
FP-RC0603FR-100RL_0603-MFG [mm]
  rrect13% 0.9x0.8 smd paste+0 mask+0: 1(-0.85,0) 2(0.85,0)
  silkscreen extent 0,-0.45 0,0.45, body extent -1.4,-0.55 1.4,0.55, height 0.25
FP-SF-3812F2000T-2_3812-MFG [mm]
  rrect3% 3.25x3.43 smd paste+0 mask+0: 1(-4.675,0) 2(4.675,0)
  silkscreen extent -2.68,-1.65 2.68,1.65, body extent -6.4,-1.82 6.4,1.82, height 0.25
FP-STK-0.3P%2FM1S-x_20_STK-x.xP%2FM1S-x-MFG [mm] "Recommended Land Pattern"
  rrect7% 1.52x2.03 hole 1.2 paste-2539.97 mask+0: 1(14.13,1.1)
  rrect100% 1.52x2.03 hole 1.2 paste-2539.97 mask+0: 2(11.59,1.1) 3(9.05,1.1) 4(-11.25,1.1) 5(-13.79,1.1)
  round 4.5 hole 2.6 paste-2539.97 mask+0: 6(-5.75,8.62) 7(1.05,8.62) 8(-5.75,-7.38) 9(1.05,-7.38)
  silkscreen extent -18.55,-6.6 18.55,7.33, body extent -18.55,-8.28 18.55,9.51, height 31.1
FP-WNSC6D02650P6X_SOD123-IPC_C [mm]
  rrect15% 1.007x0.682 smd paste+0 mask+0: 1(-1.576,0)
  rrect100% 1.007x0.682 smd paste+0 mask+0: 2(1.576,0)
  silkscreen extent -2.04,-0.8 1.35,0.97, body extent -1.85,-0.8 1.85,0.8, height 1.25
FP-WNSC6D20650B6J_TO263-MFG [mm] "Recommended Land Pattern"
  rrect8% 1.3x3.1 smd paste+0 mask+0: 1(-2.54,-6.5) 3(2.54,-6.5)
  round 6.75 smd paste+0 mask+0: 4(0,4.132)
  Top Layer region: -5.3,8.05 5.3,8.05 5.3,5.8 3.75,5.8 3.75,-0.4 -3.75,-0.4 -3.75,5.8 -5.3,5.8
  silkscreen extent -5.23,-7.75 5.23,-0.78, body extent -5.4,-8.15 5.4,8.15, height 0.25
FP-WS8712x-C5_SMD31-MFG [mm] "Recommended Land Pattern"
  rrect11% 1.6x0.9 smd paste+0 mask+0: 1(-9,8.91) 2(-9,7.64) 3(-9,6.37) 4(-9,5.1) 5(-9,3.83) 6(-9,2.56) 7(-9,1.29) 8(-9,0.02) 9(-9,-1.25) 10(-9,-2.52) 11(-9,-3.79) 12(-9,-5.06) 13(-9,-6.33) 14(-9,-7.6) 15(9,-7.6) 16(9,-6.33) 17(9,-5.06) 18(9,-3.79) 19(9,-2.52) 20(9,-1.25) 21(9,0.02) 22(9,1.29) 23(9,2.56) 24(9,3.83) 25(9,5.1) 26(9,6.37) 27(9,7.64) 28(9,8.91)
  rrect11% 0.9x1.6 smd paste+0 mask+0: 29(4,10.6) 30(2.73,10.6) 31(1.46,10.6)
  silkscreen extent -9.72,-10.68 9.08,10.68, body extent -9,-10.6 9,10.6, height 2.8
FP-YXA80182T-3_pth4-MFG [mm] "Recommended Land Pattern"
  rrect2% 4.55x4.55 hole 3 paste-2539.97 mask+0: 1(-6,-13)
  round 4.55 hole 3 paste-2539.97 mask+0: 2(6,-13) 3(6,13) 4(-6,13)
  silkscreen extent -15,-16.65 15,16, body extent -15,-16 15,16, height 24
FP-ZRB18AR61E106ME01L_0603-MFG [mm]
  rrect13% 0.75x0.9 smd paste+0 mask+0: 1(-0.775,0) 2(0.775,0)
  silkscreen extent 0,-0.5 0,0.5, body extent -1.25,-0.6 1.25,0.6, height 0.25
IEC_HighVoltage_Medium [mm]
  silkscreen extent -5.51,-4.46 5.51,5.09
IEC_HotSurface_Medium [mm]
  silkscreen extent -5.51,-4.76 5.51,4.78
Keystone5001 [mil] "For Keystone 500x miniature loop terminals"
  round 80 hole 40: 1(0,0)
  silkscreen extent -52,-52 52,52, body extent -49,-49 49,49, height 182
Keystone_5017 [mm] "PC Test Point, SMT"
  rrect6% 3.43x1.78 smd: 1(0,0)
  body extent -1.35,-0.51 1.35,0.51, height 1.51
KLG0016A-MFG [mm] "Recommended Land Pattern"
  rrect12% 2.5x0.85 smd paste+0 mask+0: 1(-6.75,4.2) 2(-6.75,3) 3(-6.75,1.8) 4(-6.75,0.6) 5(-6.75,-0.6) 6(-6.75,-1.8) 7(-6.75,-3) 8(-6.75,-4.2) 9(6.75,-4.2) 10(6.75,-3) 11(6.75,-1.8) 12(6.75,-0.6) 13(6.75,0.6) 14(6.75,1.8) 15(6.75,3) 16(6.75,4.2)
  silkscreen extent -8.77,-4.97 5.1,4.97, body extent -7.5,-4.96 7.5,4.96, height 2.35
Label_650x200 [mil] "Thermal Transfer Label"
  round 1 on Mech13: 0(0,0)
  silkscreen extent -325,-100 325,100, body extent -325,-100 325,100, height 1
Phoenix_1714955 [mm] "Terminal Block, 2x1, 6.35mm, TH"
  rect 1.8x1.8 hole 1.3: 1(-3.175,0)
  round 1.8 hole 1.3: 2(3.175,0)
  silkscreen extent -6.7,-7.9 6.35,4.6, body extent -6.92,-7.9 6.35,4.6, height 21.5
PM0064A-MFG [mm] "Recommended Land Pattern"
  rrect33% 1.5x0.3 smd paste+0 mask+0: 1(-5.7,3.75) 2(-5.7,3.25) 3(-5.7,2.75) 4(-5.7,2.25) 5(-5.7,1.75) 6(-5.7,1.25) 7(-5.7,0.75) 8(-5.7,0.25) 9(-5.7,-0.25) 10(-5.7,-0.75) 11(-5.7,-1.25) 12(-5.7,-1.75) 13(-5.7,-2.25) 14(-5.7,-2.75) 15(-5.7,-3.25) 16(-5.7,-3.75) 33(5.7,-3.75) 34(5.7,-3.25) 35(5.7,-2.75) 36(5.7,-2.25) 37(5.7,-1.75) 38(5.7,-1.25) 39(5.7,-0.75) 40(5.7,-0.25) 41(5.7,0.25) 42(5.7,0.75) 43(5.7,1.25) 44(5.7,1.75) 45(5.7,2.25) 46(5.7,2.75) 47(5.7,3.25) 48(5.7,3.75)
  rrect33% 0.3x1.5 smd paste+0 mask+0: 17(-3.75,-5.7) 18(-3.25,-5.7) 19(-2.75,-5.7) 20(-2.25,-5.7) 21(-1.75,-5.7) 22(-1.25,-5.7) 23(-0.75,-5.7) 24(-0.25,-5.7) 25(0.25,-5.7) 26(0.75,-5.7) 27(1.25,-5.7) 28(1.75,-5.7) 29(2.25,-5.7) 30(2.75,-5.7) 31(3.25,-5.7) 32(3.75,-5.7) 49(3.75,5.7) 50(3.25,5.7) 51(2.75,5.7) 52(2.25,5.7) 53(1.75,5.7) 54(1.25,5.7) 55(0.75,5.7) 56(0.25,5.7) 57(-0.25,5.7) 58(-0.75,5.7) 59(-1.25,5.7) 60(-1.75,5.7) 61(-2.25,5.7) 62(-2.75,5.7) 63(-3.25,5.7) 64(-3.75,5.7)
  silkscreen extent -7.12,-5.1 5.1,5.1, body extent -6,-6 6,6, height 1.6
Samtec_TSW-110-08-x-S [mm] "Header, 2.54mm, 10x1, TH"
  rrect50% 1.55x1.55 hole 1.02: 1(-11.43,0)
  round 1.55 hole 1.02: 2(-8.89,0) 3(-6.35,0) 4(-3.81,0) 5(-1.27,0) 6(1.27,0) 7(3.81,0) 8(6.35,0) 9(8.89,0) 10(11.43,0)
  silkscreen extent -12.7,-1.27 12.83,1.7, body extent -12.7,-1.27 12.83,1.27, height 8.38
SMA [mm] "Molded Diode, 2-Leads, Body 4.3x2.6mm, IPC Medium Density, based on OnSemi component dimensions and land pattern"
  rect 2x2 smd: 1(-2,0) 2(2,0)
  silkscreen extent -3.66,-1.57 2.79,1.58, body extent -2.6,-1.3 2.6,1.3, height 2.42
SOD-123 [mm] "On Semi recommended land pattern"
  rect 0.915x1.22 smd: 1(-1.637,0) 2(1.637,0)
  silkscreen extent -2.74,-1.17 2.03,1.17, body extent -1.93,-0.9 1.93,0.9, height 1.35
SOD-323 [mm] "NXP recommended land pattern"
  rect 0.6x0.6 smd paste-0.05: 1(-1.1,0) 2(1.1,0)
  silkscreen extent -2.06,-0.86 1.53,0.86, body extent -1.3,-0.67 1.3,0.68, height 1.1
SRN3015 [mm] "SMD, 2-Leads, Body 3x3mm"
  rect 1x2.7 smd: 1(-1.1,0) 2(1.1,0)
  silkscreen extent -0.5,-1.7 0.5,1.7
Sullins_PBC03DAAN [mm] "Sullins 100mil, 2x3, 230 mil above insulator"
  rect 1.65x1.65 hole 1.016: 1(-1.27,2.54)
  round 1.65 hole 1.016: 2(1.27,2.54) 3(-1.27,0) 4(1.27,0) 5(-1.27,-2.54) 6(1.27,-2.54)
  silkscreen extent -2.67,-3.81 2.54,4.58, body extent -2.54,-3.81 2.54,3.81, height 8.38
Sullins_xxC04SAAN [mm] "Header, 2.54 mm, 4x1, TH"
  rect 1.55x1.55 hole 1.016: 1(-3.81,0)
  round 1.55 hole 1.016: 2(-1.27,0) 3(1.27,0) 4(3.81,0)
  silkscreen extent -5.08,-1.27 5.08,1.6, body extent -5.08,-1.27 5.08,1.27, height 8.38
Sullins_xxxC016SAAN [mm] "Header, 2.54 mm, 16x1, TH"
  rect 1.5x1.5 hole 1: 1(-19.05,0)
  round 1.5 hole 1: 2(-16.51,0) 3(-13.97,0) 4(-11.43,0) 5(-8.89,0) 6(-6.35,0) 7(-3.81,0) 8(-1.27,0) 9(1.27,0) 10(3.81,0) 11(6.35,0) 12(8.89,0) 13(11.43,0) 14(13.97,0) 15(16.51,0) 16(19.05,0)
  silkscreen extent -20.32,-1.27 20.32,1.6, body extent -20.32,-1.27 20.32,1.27, height 8.34
TI_Stacked_Overlay_Small [mm]
  silkscreen extent -10.63,-2.49 10.63,2.49
UWT_630x770 [mm] "SMD, 2-Leads, Dia 6.3mm"
  rrect6% 3.5x1.6 smd: 1(-2.7,0) 2(2.7,0)
  body extent -3.5,-3.3 3.5,3.3, height 8
WEEE_Minimum [mm] "WEEElie bin"
  silkscreen extent -2.42,-4.38 2.52,2.65
WURTH_61300611121 [mm] "Header, 2.54mm, 6x1, TH"
  rrect50% 1.65x1.65 hole 1.15: 1(-6.35,0)
  round 1.65 hole 1.15: 2(-3.81,0) 3(-1.27,0) 4(1.27,0) 5(3.81,0) 6(6.35,0)
  body extent -7.62,-1.27 7.62,1.27, height 8.54
Wurth_WP-THRBU [mm] "Power Element Bush, M3, TH"
  round 3.2 hole 1.85: 1(-2.935,-2.935) 1(-2.935,2.935) 1(2.935,-2.935) 1(2.935,2.935)
  round 3.1 on Top Paste: ""(-2.935,-2.935) ""(-2.935,2.935) ""(2.935,-2.935) ""(2.935,2.935)
  round 3 hole 3.3 unplated mask+0.102: ""(0,0)
  silkscreen extent -3.5,-3.5 3.5,3.5, body extent -3.5,-3.5 3.5,3.5, height 3
YJK0003A [mm] "SMD, 3-Leads, Body 1.49x0.73mm"
  rrect50% 0.2x0.39 on Top Paste: 1(-0.525,0) 2(0,0) 3(0.525,0)
  rrect80% 0.25x0.49 smd paste-0.15 mask-0.05: 1(-0.5,0) 2(0,0) 3(0.5,0)
  silkscreen extent -0.9,-0.5 0.9,0.5, body extent -0.75,-0.37 0.74,0.36, height 0.35

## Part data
C1 C3 C5 C6: library part CMP-0033686-1, "ALH82, Aluminum Electrolytic, 160 uF, 20%, 600 VDC, -40/+105°C", Leakage Current=288uA, Manufacturer=KEMET, Operating Temperature Range="-40°C to +105°C", Tolerance_%=20%, ValueDisplayed=160uF
C2 C4 C12 C13: library part CMP-0128404-1, "Film Capacitor 5uF 10% 600V 32x14x28mm TH", Manufacturer=Jianghai, Operating Temperature Range="-40°C to +105°C", Tolerance_%=10%, ValueDisplayed=5uF
C7: library part CMP-0086078-1, "CAP, CERM, 2200 pF, 3000 V,+/- 10%, B, Dia 12.5mm", Cap_Case=12.5x6x16.5mm, Manufacturer=TDK, TempCo=B, Tolerance_%=10%, Value2=3000V, ValueDisplayed=2200pF
C8 C20 C24 C30: library part CMP-0042924-1, "6800 pF Film Capacitor 300V 1500V (1.5kV) Polypropylene (PP), Metallized Radial", Digikey Part Number=399-R413F168050T0K-ND, Manufacturer=KEMET, Mouser Part Number=80-R413F168050T0K, Operating Temperature Range="-40°C to +125°C", Tolerance_%=10%, ValueDisplayed=6800pF, Voltage Ac Rating Y=300V
C9 C110_U_TIDA-011008_ACDC_Leg1 C110_U_TIDA-011008_ACDC_Leg2 C123_U_TIDA-011008_ACDC_Leg1 C123_U_TIDA-011008_ACDC_Leg2: library part CMP-0009063-2, "CAP, CERM, 22 uF, 25 V, +/- 20%, X5R, 1210", Cap_Case=1210, Manufacturer=AVX, Supplier Part Number 1=96M1536, TempCo=X5R, Tolerance_%=20%, Value1=Unknown, Value2=25V, ValueDisplayed=22uF
C10 C111_U_TIDA-011008_ACDC_Leg1 C111_U_TIDA-011008_ACDC_Leg2 C112_U_TIDA-011008_ACDC_Leg1 C112_U_TIDA-011008_ACDC_Leg2 C124_U_TIDA-011008_ACDC_Leg1 C124_U_TIDA-011008_ACDC_Leg2: library part CMP-0750154-1, "CAP, CERM, 10 µF, 25 V,+/- 10%, X7R, AEC-Q200 Grade 1, 1206", Cap_Case=1206, Manufacturer="Taiyo Yuden", TempCo=X7R, Tolerance_%=10%, Value2=25V, ValueDisplayed=10µF
C11 C28 C29 C84 C89 C108_U_TIDA-011008_ACDC_Leg1 C108_U_TIDA-011008_ACDC_Leg2 C109_U_TIDA-011008_ACDC_Leg1 C109_U_TIDA-011008_ACDC_Leg2 C113_U_TIDA-011008_ACDC_Leg1 C113_U_TIDA-011008_ACDC_Leg2 C117_U_TIDA-011008_ACDC_Leg1 C117_U_TIDA-011008_ACDC_Leg2 C125_U_TIDA-011008_ACDC_Leg1 C125_U_TIDA-011008_ACDC_Leg2: library part CMP-0095617-1, "0603 50 V 0.1 uF X7R ±10% Tolerance SMT Multilayer Ceramic Capacitor", Digikey Part Number=490-8020-1-ND, Manufacturer=Murata, Mouser Part Number=81-GCM188R71H104KA7J, Operating Temperature Range="-55°C to +125°C", TempCo=15%, Temperature Characteristic=X7R, Tolerance_%=10%, ValueDisplayed=0.1uF
C14 C15 C114_U_TIDA-011008_ACDC_Leg1 C114_U_TIDA-011008_ACDC_Leg2 C115_U_TIDA-011008_ACDC_Leg1 C115_U_TIDA-011008_ACDC_Leg2 C116_U_TIDA-011008_ACDC_Leg1 C116_U_TIDA-011008_ACDC_Leg2 C126_U_TIDA-011008_ACDC_Leg1 C126_U_TIDA-011008_ACDC_Leg2 C127_U_TIDA-011008_ACDC_Leg1 C127_U_TIDA-011008_ACDC_Leg2: library part CMP-0045670-1, "220 pF ±5% 50V Ceramic Capacitor C0G, NP0 0603 (1608 Metric)", Digikey Part Number=399-C0603C221J5GAC7867CT-ND, Manufacturer=KEMET, Operating Temperature Range="-55°C to +125°C", TempCo=30ppm/°C, Temperature Characteristic=C0G, Tolerance_%=5%, ValueDisplayed=220pF
C16: library part CMP-0128435-1, "Film Capacitor 3uF 10% 600V 32x11x20mm TH", Manufacturer=Jianghai, Operating Temperature Range="-40°C to +105°C", Tolerance_%=10%, ValueDisplayed=3uF
C17 C18 C119_U_TIDA-011008_ACDC_Leg1 C119_U_TIDA-011008_ACDC_Leg2 C121_U_TIDA-011008_ACDC_Leg1 C121_U_TIDA-011008_ACDC_Leg2 C122_U_TIDA-011008_ACDC_Leg1 C122_U_TIDA-011008_ACDC_Leg2: library part CMP-0009324-2, "CAP, CERM, 0.1 uF, 1000 V, +/- 10%, X7R, 1812", Cap_Case=1812, Manufacturer=Kemet, Supplier Part Number 1=399-6493-1-ND, TempCo=X7R, Tolerance_%=10%, Value1=Unknown, Value2=1000V, ValueDisplayed=0.1uF
C19_U_TIDA-011008_ACDC_Leg1 C19_U_TIDA-011008_ACDC_Leg2: library part CMP-0007424-4, "CAP, CERM, 0.47 uF, 25 V, +/- 10%, X7R, 0603", Cap_Case=0603, Manufacturer=MuRata, Supplier Part Number 1=490-3291-1-ND, TempCo=X7R, Tolerance_%=10%, Value1=Unknown, Value2=25V, ValueDisplayed=0.47uF
C21 C36 C71 C72 C73 C74: library part CMP-0086152-1, "CAP, CERM, 1 µF, 25 V,+/- 10%, X5R, 0603", Cap_Case=0603, Manufacturer="Taiyo Yuden", TempCo=X5R, Tolerance_%=10%, Value2=25V, ValueDisplayed=1µF
C22 C42 C49 C77 C78 C81 C118_U_TIDA-011008_ACDC_Leg1 C118_U_TIDA-011008_ACDC_Leg2 C130 C136: library part CMP-0006752-5, "CAP, CERM, 0.1 uF, 25 V, +/- 5%, X7R, 0603", Cap_Case=0603, Manufacturer=AVX, Supplier Part Number 1=478-3713-1-ND, TempCo=X7R, Tolerance_%=5%, Value1="0.05 ohm", Value2=25V, ValueDisplayed=0.1uF
C23: library part CMP-0007197-4, "CAP, CERM, 220 pF, 50 V, +/- 5%, C0G/NP0, 0603", Cap_Case=0603, Manufacturer=MuRata, Supplier Part Number 1=490-1435-1-ND, TempCo=C0G/NP0, Tolerance_%=5%, Value1=Unknown, Value2=50V, ValueDisplayed=220pF
C25 C31: library part CMP-0009613-2, "CAP, CERM, 2200 pF, 300 V, +/- 20%, E, TH, 2- Leads, Body 9x7mm, Pin Spacing 7.5mm", Cap_Case=9x7x9mm, Manufacturer=MuRata, Supplier Part Number 1=DE6E3KJ222MN3A-ND, TempCo=E, Tolerance_%=20%, Value1=Unknown, Value2=300V, ValueDisplayed=2200pF
C26 C27: library part CMP-0128465-1, "Film Capacitor 4.7uF 10% 305VAC 32x22x37mm TH", Manufacturer=Jianghai, Operating Temperature Range="-40°C to +110°C", Tolerance_%=10%, ValueDisplayed=4.7uF
C32 C37 C38 C39 C45 C53 C54 C55 C61 C62 C132 C134 C140 C141: library part CMP-0007442-5, "CAP, CERM, 220 pF, 50 V, +/- 10%, X7R, 0603", Cap_Case=0603, Manufacturer=MuRata, Supplier Part Number 1=490-1483-1-ND, TempCo=X7R, Tolerance_%=10%, Value1=Unknown, Value2=50V, ValueDisplayed=220pF
C33 C40: library part CMP-0006638-2, "CAP, CERM, 1000 pF, 16 V, +/- 10%, X7R, 0402", Cap_Case=0402, Manufacturer=MuRata, Supplier Part Number 1=GRM155R71C102KA01D-ND, TempCo=X7R, Tolerance_%=10%, Value1=Unknown, Value2=16V, ValueDisplayed=1000pF
C34 C41: library part CMP-0007470-5, "CAP, CERM, 0.1 uF, 100 V, +/- 10%, X7R, 0603", Cap_Case=0603, Manufacturer=MuRata, Supplier Part Number 1=490-6439-1-ND, TempCo=X7R, Tolerance_%=10%, Value1=Unknown, Value2=100V, ValueDisplayed=0.1uF
C35: library part CMP-0750039-1, "CAP, CERM, 0.01 µF, 50 V,+/- 10%, X7R, 0603", Cap_Case=0603, Manufacturer="Wurth Elektronik", TempCo=X7R, Tolerance_%=10%, Value2=50V, ValueDisplayed=0.01µF
C43 C48: library part CMP-0006979-5, "CAP, CERM, 0.1 uF, 25 V, +/- 10%, X7R, 0603", Cap_Case=0603, Manufacturer=Kemet, Supplier Part Number 1=399-5345-1-ND, TempCo=X7R, Tolerance_%=10%, Value1=Unknown, Value2=25V, ValueDisplayed=0.1uF
C44 C82 C83 C85 C86 C87 C88 C90 C91 C96 C101 C102 C129: library part CMP-0006895-4, "CAP, CERM, 220 pF, 50 V, +/- 10%, X7R, 0603", Cap_Case=0603, Manufacturer=Kemet, Supplier Part Number 1=399-1071-1-ND, TempCo=X7R, Tolerance_%=10%, Value1=Unknown, Value2=50V, ValueDisplayed=220pF
C46 C47: library part CMP-0007189-4, "CAP, CERM, 1600 pF, 50 V, +/- 5%, C0G/NP0, 0603", Cap_Case=0603, Manufacturer=MuRata, Supplier Part Number 1=490-1456-1-ND, TempCo=C0G/NP0, Tolerance_%=5%, Value1=Unknown, Value2=50V, ValueDisplayed=1600pF
C50 C51 C52 C56 C57 C58 C131 C133: library part CMP-0007225-4, "CAP, CERM, 560 pF, 50 V, +/- 5%, C0G/NP0, 0603", Cap_Case=0603, Manufacturer=MuRata, Supplier Part Number 1=490-1445-1-ND, TempCo=C0G/NP0, Tolerance_%=5%, Value1=Unknown, Value2=50V, ValueDisplayed=560pF
C59 C60 C63 C64: library part CMP-0007194-4, "CAP, CERM, 200 pF, 50 V, +/- 5%, C0G/NP0, 0603", Cap_Case=0603, Manufacturer=MuRata, Supplier Part Number 1=490-1434-1-ND, TempCo=C0G/NP0, Tolerance_%=5%, Value1=Unknown, Value2=50V, ValueDisplayed=200pF
C65 C66 C67 C68 C106 C107: library part CMP-0089959-1, "0.1µF ±10% 25V Ceramic Capacitor X8R 0603 (1608 Metric)", Digikey Part Number=445-2500-1-ND, Manufacturer="TDK Corporation", Mouser Part Number=810-C1608X8R1E104K, Operating Temperature Range="-55°C to +150°C", TempCo=15%, Temperature Characteristic=X8R, Tolerance_%=10%, ValueDisplayed=100nF
C69: library part CMP-0081462-1, "CAP, AL, 100 µF, 25 V, +/- 20%, SMD", Cap_Case=6.3x7.7mm, Manufacturer=Nichicon, Supplier Part Number 1=493-2190-1-ND, Tolerance_%=20%, Value2=25V, ValueDisplayed=100µF
C70: library part CMP-0088731-1, "0.1µF ±10% 50V Ceramic Capacitor X7R 0805 (2012 Metric)", Digikey Part Number=490-16485-1-ND, Manufacturer=Murata, Mouser Part Number=81-GCE21BR71H104KA1L, Operating Temperature Range="-55°C to +125°C", TempCo=15%, Temperature Characteristic=X7R, Tolerance_%=10%, ValueDisplayed=0.1uF
C75 C76 C79 C80 C135 C138 C139: library part CMP-0094458-1, "10µF ±20% 25V Ceramic Capacitor X5R 0603 (1608 Metric)", Digikey Part Number=490-10991-1-ND, Manufacturer="Murata Electronics", Mouser Part Number=81-ZRB18AR61E106ME1L, Operating Temperature Range="-55°C to +85°C", Temperature Characteristic=X5R, Tolerance_%=20%, ValueDisplayed=10uF
C92 C93 C94 C99 C100: library part CMP-0861000-1, "CAP, CERM, 0.1 µF, 25 V,+/- 10%, X8L, AEC-Q200 Grade 0, 0402", Cap_Case=0402, Manufacturer=MuRata, TempCo=X8L, Tolerance_%=10%, Value2=25V, ValueDisplayed=0.1µF
C95: library part CMP-0125957-1, "Chip Multilayer Ceramic Capacitors for General Purpose, 0603, 10uF, X7R, 15%, 10%, 10V", Manufacturer=Murata, Operating Temperature Range="-55°C to +125°C", TempCo=15%, Temperature Characteristic=X7R, Tolerance_%=10%, ValueDisplayed=10uF
C97 C98 C103 C104 C128: library part CMP-0079605-1, "CAP, CERM, 2.2 µF, 16 V,+/- 10%, X7R, 0603", Cap_Case=0603, Manufacturer="Yageo America", Supplier Part Number 1=311-3490-1-ND, TempCo=X7R, Tolerance_%=10%, Value2=16V, ValueDisplayed=2.2µF
C105: library part CMP-0123328-1, "22 µF ±20% 25V Ceramic Capacitor X5S 0603 (1608 Metric)", Digikey Part Number=490-GRM188C61E226ME01JCT-ND, Manufacturer=Murata, Mouser Part Number=81-GRM188C61E226ME1J, Operating Temperature Range="-55°C to +85°C", TempCo=22%, Temperature Characteristic=X5S, Tolerance_%=20%, ValueDisplayed=22uF
C120_U_TIDA-011008_ACDC_Leg1 C120_U_TIDA-011008_ACDC_Leg2: library part CMP-0006813-4, "CAP, CERM, 1000 pF, 10 V, +/- 10%, X7R, 0603", Cap_Case=0603, Manufacturer=AVX, Supplier Part Number 1=0603ZC102KAT2A-ND, TempCo=X7R, Tolerance_%=10%, Value1=Unknown, Value2=10V, ValueDisplayed=1000pF
C137: library part CMP-0007378-5, "CAP, CERM, 0.1 uF, 16 V, +/- 10%, X7R, 0603", Cap_Case=0603, Manufacturer=MuRata, Supplier Part Number 1=490-1532-1-ND, TempCo=X7R, Tolerance_%=10%, Value1=Unknown, Value2=16V, ValueDisplayed=0.1uF
D1 D15: library part CMP-0128428-1, "Silicon Carbide Diode 650 V 20A Surface Mount D2PAK", Digikey Part Number=1740-WNSC6D20650B6JCT-ND, Forward Current=20A, Manufacturer="WeEn Semiconductors", Max Surge Forward Current=120A, Operating Temperature Range="-55°C to +175°C", Peak Reverse Current=1uA, ValueDisplayed=780pF
D2 D3: library part CMP-0028389-2, "Diode, Schottky, 60 V, 1 A, SMA", Manufacturer="Diodes Inc.", Value1=1A, Value2=0.7V
D6 D7 D8: library part CMP-0093310-1, "Standard LEDs - SMD Green TOPLED E 1608", Color=Green, Forward Current=2mA, Manufacturer="Osram Opto", Mouser Part Number=720-KGDELLS122A4849, Operating Temperature Range="-40°C to +110°C"
D10 D11 D12: library part CMP-0005826-3, "Diode, TVS, Uni, 3.3 V, SOD-323", Manufacturer="Protek Devices", Value1=350W
D13_U_TIDA-011008_ACDC_Leg1 D13_U_TIDA-011008_ACDC_Leg2: library part CMP-0128427-1, "Rectifier Diode, Schottky, 1 Phase, 1 Element, 2A, 700V V(RRM), Silicon Carbide", Forward Current=2A, Manufacturer="WeEn Semiconductors", Max Surge Forward Current=14A, Mouser Part Number=771-WNSC6D02650P6X, Operating Temperature Range="-55°C to +175°C", Peak Reverse Current=0.2uA, ValueDisplayed=103pF
D14_U_TIDA-011008_ACDC_Leg1 D14_U_TIDA-011008_ACDC_Leg2: library part CMP-0005769-4, "Diode, Zener, 16 V, 500 mW, AEC-Q101, SOD-123", Manufacturer="Diodes Inc.", Power_W=500mW, Value1=0.5W
F1 F2: library part CMP-0042962-1, "20 A 250 V AC 80 V DC Fuse Board Mount (Cartridge Style Excluded) Surface Mount 2-SMD, Square End Block", Digikey Part Number=SF-3812F2000T-2CT-ND, Fuse Current=20A, Fuse Interrupt Dc Current=300A, Manufacturer=Bourns, Mouser Part Number=652-SF-3812F2000T-2, Operating Temperature Range="-55°C to +125°C"
FB1 FB2 FB3 FB4 FB5 FB6 FB7_U_TIDA-011008_ACDC_Leg1 FB7_U_TIDA-011008_ACDC_Leg2 FB8 FB9: library part CMP-0037505-1, "600 Ohms @ 100 MHz 1 Power, Signal Line Ferrite Bead 0603 (1608 Metric) 1A 200mOhm", Digikey Part Number=MH1608-601YCT-ND, Impedance At Frequency="600Ω @ 100MHz", Manufacturer=Bourns, Mouser Part Number=652-MH1608-601Y, Operating Temperature Range="-55°C to +125°C", Test Frequency=100MHz, Tolerance_%=25%
FID1 FID2 FID3: library part CMP-0077181-1, "Fiducial mark.  There is nothing to buy or mount.", Manufacturer=N/A
J1 J2 J4 J5 J6 J7 J8 J9 J10: library part CMP-0078526-1, "Power Element Bush, M3, TH", Current_A=50A, Manufacturer="Wurth Elektronik", Supplier Part Number 1=732-10882-1-ND
J3: library part CMP-0055505-1, "Terminal Block, 2x1, 6.35mm, Green, TH", Color=Green, Manufacturer="Phoenix Contact", Supplier Part Number 1=277-1269-ND
J11: library part CMP-0040211-1, "Power Barrel Connector Jack 2.10mm ID (0.083\"), 5.50mm OD (0.217\") Through Hole", Current_A=3A, Digikey Part Number=732-5931-ND, Manufacturer="Wurth Electronics", Mouser Part Number=710-694106402002, Operating Temperature Range="-40°C to +85°C", Voltage_V=30V
J12: library part CMP-0055600-1, "Header, 2.54mm, 10x1, Gold, TH", Color=Black, Current_A=6.3A, Manufacturer=Samtec, Supplier Part Number 1=SAM1038-10-ND, Voltage_V=550V
J13 J14 J15 J18 J19 J22: library part CMP-0054583-1, "Header, 2.54 mm, 4x1, Gold, TH", Color=Black, Current_A=3A, Manufacturer="Sullins Connector Solutions", Supplier Part Number 1=S1011E-04-ND, Voltage_V=1.8kV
